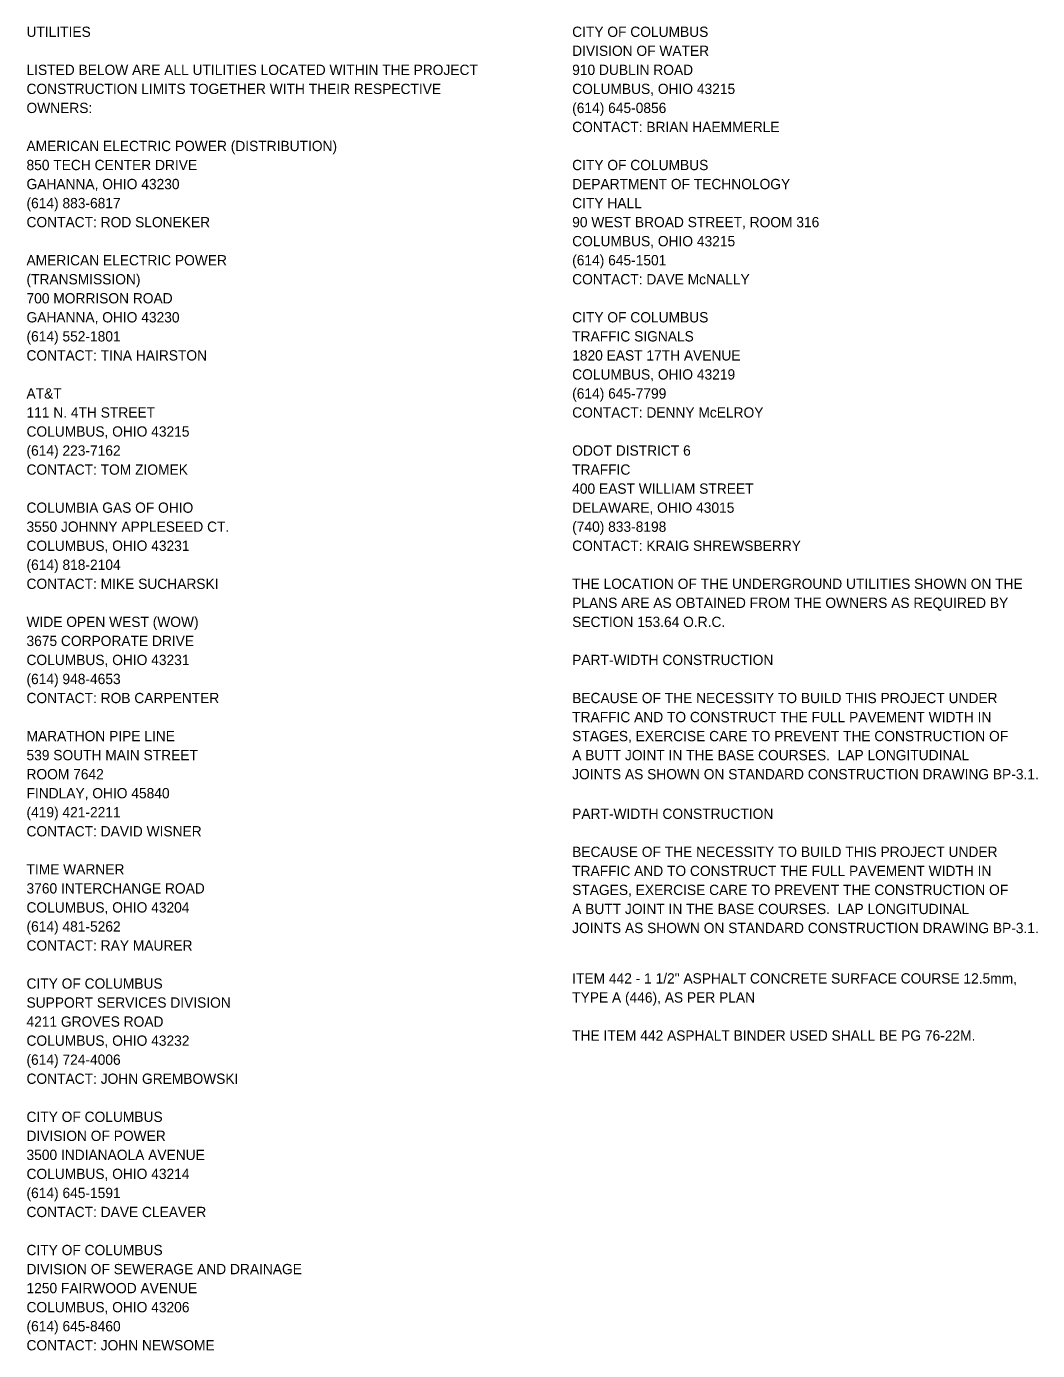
# Model space of a CAD drawing. Extents: x -25.6 to 66.7, y -23.1 to 37.2.
# Drawn here: x -25.64 to -11.89, y -4.38 to 13.63 of the extents above; entities that cross this region are included whole.
import ezdxf

# ---------------------------------------------------------------- set-up
doc = ezdxf.new("R2010")
doc.units = 0
doc.layers.add('SH_Text', color=7, linetype='Continuous')
doc.layers.add('TX_P_50', color=7, linetype='Continuous')

msp = doc.modelspace()

# ---------------------------------------------------------------- texts
at = {"layer": 'SH_Text'}
for s, p in [('CITY OF COLUMBUS ', (-18.22, 13.492)), ('DIVISION OF WATER', (-18.22, 13.233)), ('910 DUBLIN ROAD', (-18.22, 12.974)), ('COLUMBUS, OHIO 43215', (-18.22, 12.715)), ('(614) 645-0856', (-18.22, 12.456)), ('CONTACT: BRIAN HAEMMERLE', (-18.22, 12.197)), ('CITY OF COLUMBUS ', (-18.22, 11.679)), ('DEPARTMENT OF TECHNOLOGY', (-18.22, 11.42)), ('CITY HALL', (-18.22, 11.161)), ('90 WEST BROAD STREET, ROOM 316', (-18.22, 10.902)), ('COLUMBUS, OHIO 43215', (-18.22, 10.643)), ('(614) 645-1501', (-18.22, 10.384)), ('CONTACT: DAVE McNALLY', (-18.22, 10.125)), ('CITY OF COLUMBUS', (-18.22, 9.607)), ('TRAFFIC SIGNALS', (-18.22, 9.348)), ('1820 EAST 17TH AVENUE', (-18.22, 9.089)), ('COLUMBUS, OHIO 43219', (-18.22, 8.83)), ('(614) 645-7799', (-18.22, 8.571)), ('CONTACT: DENNY McELROY', (-18.22, 8.312)), ('ODOT DISTRICT 6', (-18.22, 7.794)), ('TRAFFIC', (-18.22, 7.535)), ('400 EAST WILLIAM STREET', (-18.22, 7.276)), ('DELAWARE, OHIO 43015', (-18.22, 7.017)), ('(740) 833-8198', (-18.22, 6.758)), ('CONTACT: KRAIG SHREWSBERRY', (-18.22, 6.499)), ('THE LOCATION OF THE UNDERGROUND UTILITIES SHOWN ON THE', (-18.22, 5.981)), ('PLANS ARE AS OBTAINED FROM THE OWNERS AS REQUIRED BY', (-18.22, 5.722)), ('SECTION 153.64 O.R.C.', (-18.22, 5.463)), ('PART-WIDTH CONSTRUCTION', (-18.22, 4.945)), ('BECAUSE OF THE NECESSITY TO BUILD THIS PROJECT UNDER', (-18.22, 4.427)), ('TRAFFIC AND TO CONSTRUCT THE FULL PAVEMENT WIDTH IN', (-18.22, 4.168)), ('STAGES, EXERCISE CARE TO PREVENT THE CONSTRUCTION OF', (-18.22, 3.909)), ('A BUTT JOINT IN THE BASE COURSES.  LAP LONGITUDINAL', (-18.22, 3.65)), ('JOINTS AS SHOWN ON STANDARD CONSTRUCTION DRAWING BP-3.1.', (-18.22, 3.391)), ('PART-WIDTH CONSTRUCTION', (-18.22, 2.852)), ('BECAUSE OF THE NECESSITY TO BUILD THIS PROJECT UNDER', (-18.22, 2.334)), ('TRAFFIC AND TO CONSTRUCT THE FULL PAVEMENT WIDTH IN', (-18.22, 2.075)), ('STAGES, EXERCISE CARE TO PREVENT THE CONSTRUCTION OF', (-18.22, 1.816)), ('A BUTT JOINT IN THE BASE COURSES.  LAP LONGITUDINAL', (-18.22, 1.557)), ('JOINTS AS SHOWN ON STANDARD CONSTRUCTION DRAWING BP-3.1.', (-18.22, 1.298)), ('ITEM 442 - 1 1/2" ASPHALT CONCRETE SURFACE COURSE 12.5mm, ', (-18.22, 0.612)), ('TYPE A (446), AS PER PLAN', (-18.22, 0.353)), ('THE ITEM 442 ASPHALT BINDER USED SHALL BE PG 76-22M.', (-18.22, -0.165))]:
    msp.add_text(s, height=0.14, dxfattribs=at).set_placement(p)
at = {"layer": 'TX_P_50'}
for s, p in [('UTILITIES', (-25.64, 13.492)), ('LISTED BELOW ARE ALL UTILITIES LOCATED WITHIN THE PROJECT', (-25.64, 12.974)), ('CONSTRUCTION LIMITS TOGETHER WITH THEIR RESPECTIVE', (-25.64, 12.715)), ('OWNERS: ', (-25.64, 12.456)), ('AMERICAN ELECTRIC POWER (DISTRIBUTION)', (-25.64, 11.938)), ('850 TECH CENTER DRIVE', (-25.64, 11.679)), ('GAHANNA, OHIO 43230', (-25.64, 11.42)), ('(614) 883-6817', (-25.64, 11.161)), ('CONTACT: ROD SLONEKER', (-25.64, 10.902)), ('AMERICAN ELECTRIC POWER', (-25.64, 10.384)), ('(TRANSMISSION)', (-25.64, 10.125)), ('700 MORRISON ROAD', (-25.64, 9.866)), ('GAHANNA, OHIO 43230', (-25.64, 9.607)), ('(614) 552-1801', (-25.64, 9.348)), ('CONTACT: TINA HAIRSTON', (-25.64, 9.089)), ('AT&T ', (-25.64, 8.571)), ('111 N. 4TH STREET', (-25.64, 8.312)), ('COLUMBUS, OHIO 43215', (-25.64, 8.053)), ('(614) 223-7162', (-25.64, 7.794)), ('CONTACT: TOM ZIOMEK', (-25.64, 7.535)), ('COLUMBIA GAS OF OHIO', (-25.64, 7.017)), ('3550 JOHNNY APPLESEED CT.', (-25.64, 6.758)), ('COLUMBUS, OHIO 43231', (-25.64, 6.499)), ('(614) 818-2104', (-25.64, 6.24)), ('CONTACT: MIKE SUCHARSKI', (-25.64, 5.981)), ('WIDE OPEN WEST (WOW)', (-25.64, 5.463)), ('3675 CORPORATE DRIVE', (-25.64, 5.204)), ('COLUMBUS, OHIO 43231', (-25.64, 4.945)), ('(614) 948-4653', (-25.64, 4.686)), ('CONTACT: ROB CARPENTER', (-25.64, 4.427)), ('MARATHON PIPE LINE', (-25.64, 3.909)), ('539 SOUTH MAIN STREET', (-25.64, 3.65)), ('ROOM 7642', (-25.64, 3.391)), ('FINDLAY, OHIO 45840', (-25.64, 3.132)), ('(419) 421-2211', (-25.64, 2.873)), ('CONTACT: DAVID WISNER', (-25.64, 2.614)), ('TIME WARNER', (-25.64, 2.096)), ('3760 INTERCHANGE ROAD', (-25.64, 1.837)), ('COLUMBUS, OHIO 43204', (-25.64, 1.578)), ('(614) 481-5262', (-25.64, 1.319)), ('CONTACT: RAY MAURER', (-25.64, 1.06)), ('CITY OF COLUMBUS', (-25.64, 0.542)), ('SUPPORT SERVICES DIVISION', (-25.64, 0.283)), ('4211 GROVES ROAD', (-25.64, 0.024)), ('COLUMBUS, OHIO 43232', (-25.64, -0.235)), ('(614) 724-4006', (-25.64, -0.494)), ('CONTACT: JOHN GREMBOWSKI', (-25.64, -0.753)), ('CITY OF COLUMBUS ', (-25.64, -1.271)), ('DIVISION OF POWER', (-25.64, -1.53)), ('3500 INDIANAOLA AVENUE', (-25.64, -1.789)), ('COLUMBUS, OHIO 43214', (-25.64, -2.048)), ('(614) 645-1591', (-25.64, -2.307)), ('CONTACT: DAVE CLEAVER', (-25.64, -2.566)), ('CITY OF COLUMBUS', (-25.64, -3.084)), ('DIVISION OF SEWERAGE AND DRAINAGE', (-25.64, -3.343)), ('1250 FAIRWOOD AVENUE', (-25.64, -3.602)), ('COLUMBUS, OHIO 43206', (-25.64, -3.861)), ('(614) 645-8460', (-25.64, -4.12)), ('CONTACT: JOHN NEWSOME', (-25.64, -4.379))]:
    msp.add_text(s, height=0.14, dxfattribs=at).set_placement(p)

doc.saveas('drawing.dxf')
